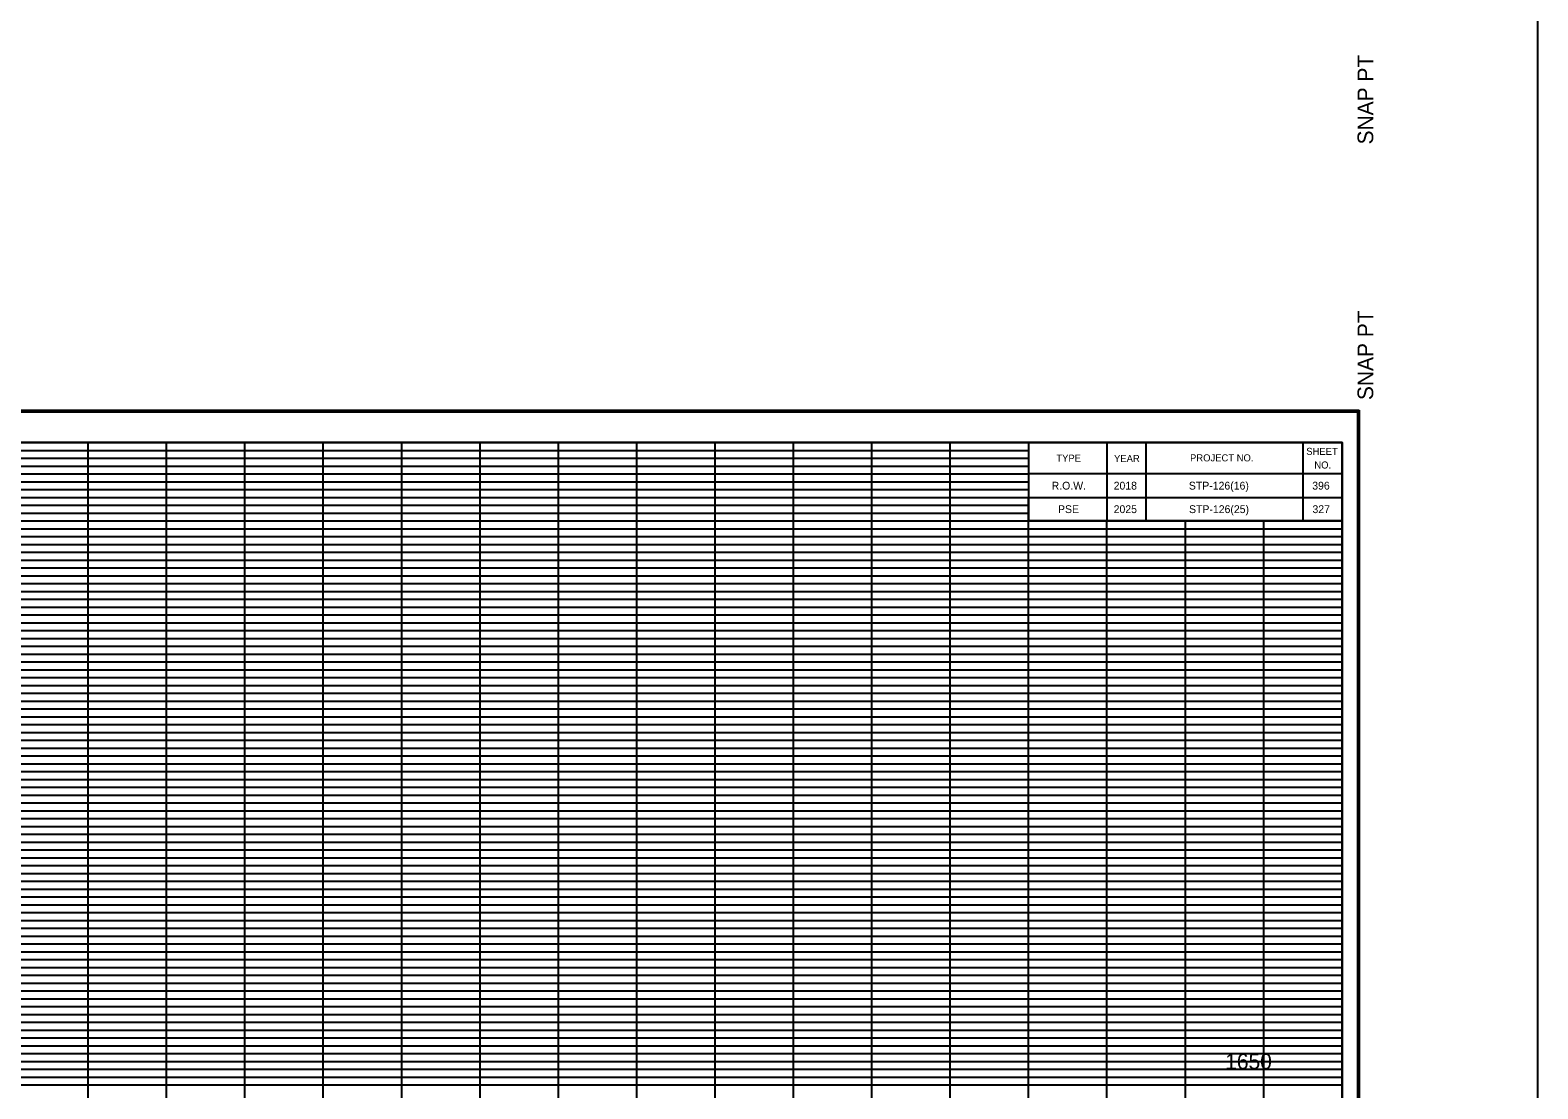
# Model space of a CAD drawing. Extents: x 955 to 1375, y 1248 to 3657.
# Drawn here: x 1152.6 to 1345, y 2477.5 to 2612.7 of the extents above; entities that cross this region are included whole.
import ezdxf

# ---------------------------------------------------------------- set-up
doc = ezdxf.new("R2010")
doc.units = 0
for name, color, linetype in [('DESIGN - SCRATCH - User 1', 7, 'Continuous'), ('DESIGN - SHEET - Corner Text', 7, 'Continuous'), ('DESIGN - SHEET - Light Grid', 7, 'Continuous'), ('DESIGN - SHEET - Linework', 7, 'Continuous'), ('DESIGN - SHEET - Plot Shape', 7, 'Continuous'), ('DESIGN - TYPICAL - Text', 7, 'Continuous'), ('DESIGN - UTILITIES - Cable (Overhead) with Text', 7, 'Continuous'), ('SURVEY - NON-TRANSPORTATION - Features Text', 7, 'Continuous')]:
    doc.layers.add(name, color=color, linetype=linetype)

# ---------------------------------------------------------------- blocks, each defined once
blk = doc.blocks.new('XSTSHT')
at = {"layer": 'DESIGN - SCRATCH - User 1'}
for p, q in [((28.5, 20.45), (28.5, 20.45)), ((29.24, 20.45), (29.24, 20.45)), ((30.49, 20.45), (30.49, 20.45)), ((31.74, 20.45), (31.74, 20.45)), ((28.5, 20.15), (28.5, 20.15)), ((29.24, 20.15), (29.24, 20.15)), ((30.49, 20.15), (30.49, 20.15)), ((31.74, 20.15), (31.74, 20.15))]:
    blk.add_line(p, q, dxfattribs=at)
at = {"layer": 'DESIGN - SHEET - Light Grid'}
for p, q in [((8, 20.9), (16, 20.9)), ((8, 20.8), (16, 20.8)), ((16, 20.9), (24, 20.9)), ((16, 20.8), (24, 20.8)), ((24, 20.9), (28, 20.9)), ((24, 20.8), (28, 20.8)), ((8, 20.7), (16, 20.7)), ((8, 20.6), (16, 20.6)), ((16, 20.7), (24, 20.7)), ((16, 20.6), (24, 20.6)), ((24, 20.7), (28, 20.7)), ((24, 20.6), (28, 20.6)), ((8, 20.5), (16, 20.5)), ((8, 20.4), (16, 20.4)), ((16, 20.5), (24, 20.5)), ((16, 20.4), (24, 20.4)), ((24, 20.5), (28, 20.5)), ((24, 20.4), (28, 20.4)), ((8, 20.3), (16, 20.3)), ((16, 20.3), (24, 20.3)), ((24, 20.3), (28, 20.3)), ((8, 20.2), (16, 20.2)), ((8, 20.1), (16, 20.1)), ((16, 20.2), (24, 20.2)), ((16, 20.1), (24, 20.1)), ((24, 20.2), (28, 20.2)), ((24, 20.1), (28, 20.1)), ((8, 19.9), (16, 19.9)), ((16, 19.9), (24, 19.9)), ((24, 19.9), (32, 19.9)), ((8, 19.8), (16, 19.8)), ((8, 19.7), (16, 19.7)), ((16, 19.8), (24, 19.8)), ((16, 19.7), (24, 19.7)), ((24, 19.8), (32, 19.8)), ((24, 19.7), (32, 19.7)), ((8, 19.6), (16, 19.6)), ((8, 19.5), (16, 19.5)), ((16, 19.6), (24, 19.6)), ((16, 19.5), (24, 19.5)), ((24, 19.6), (32, 19.6)), ((24, 19.5), (32, 19.5)), ((8, 19.4), (16, 19.4)), ((8, 19.3), (16, 19.3)), ((16, 19.4), (24, 19.4)), ((16, 19.3), (24, 19.3)), ((24, 19.4), (32, 19.4)), ((24, 19.3), (32, 19.3)), ((8, 19.2), (16, 19.2)), ((8, 19.1), (16, 19.1)), ((16, 19.2), (24, 19.2)), ((16, 19.1), (24, 19.1)), ((24, 19.2), (32, 19.2)), ((24, 19.1), (32, 19.1)), ((8, 18.9), (16, 18.9)), ((16, 18.9), (24, 18.9)), ((24, 18.9), (32, 18.9)), ((8, 18.8), (16, 18.8)), ((8, 18.7), (16, 18.7)), ((16, 18.8), (24, 18.8)), ((16, 18.7), (24, 18.7)), ((24, 18.8), (32, 18.8)), ((24, 18.7), (32, 18.7)), ((8, 18.6), (16, 18.6)), ((8, 18.5), (16, 18.5)), ((16, 18.6), (24, 18.6)), ((16, 18.5), (24, 18.5)), ((24, 18.6), (32, 18.6)), ((24, 18.5), (32, 18.5)), ((8, 18.4), (16, 18.4)), ((8, 18.3), (16, 18.3)), ((16, 18.4), (24, 18.4)), ((16, 18.3), (24, 18.3)), ((24, 18.4), (32, 18.4)), ((24, 18.3), (32, 18.3)), ((8, 18.2), (16, 18.2)), ((8, 18.1), (16, 18.1)), ((16, 18.2), (24, 18.2)), ((16, 18.1), (24, 18.1)), ((24, 18.2), (32, 18.2)), ((24, 18.1), (32, 18.1)), ((8, 17.9), (16, 17.9)), ((16, 17.9), (24, 17.9)), ((24, 17.9), (32, 17.9)), ((8, 17.8), (16, 17.8)), ((8, 17.7), (16, 17.7)), ((16, 17.8), (24, 17.8)), ((16, 17.7), (24, 17.7)), ((24, 17.8), (32, 17.8)), ((24, 17.7), (32, 17.7)), ((8, 17.6), (16, 17.6)), ((16, 17.6), (24, 17.6)), ((24, 17.6), (32, 17.6)), ((8, 17.5), (16, 17.5)), ((8, 17.4), (16, 17.4)), ((16, 17.5), (24, 17.5)), ((16, 17.4), (24, 17.4)), ((24, 17.5), (32, 17.5)), ((24, 17.4), (32, 17.4)), ((8, 17.3), (16, 17.3)), ((8, 17.2), (16, 17.2)), ((16, 17.3), (24, 17.3)), ((16, 17.2), (24, 17.2)), ((24, 17.3), (32, 17.3)), ((24, 17.2), (32, 17.2)), ((8, 17.1), (16, 17.1)), ((16, 17.1), (24, 17.1)), ((24, 17.1), (32, 17.1)), ((8, 16.9), (16, 16.9)), ((8, 16.8), (16, 16.8)), ((16, 16.9), (24, 16.9)), ((16, 16.8), (24, 16.8)), ((24, 16.9), (32, 16.9)), ((24, 16.8), (32, 16.8)), ((8, 16.7), (16, 16.7)), ((8, 16.6), (16, 16.6)), ((16, 16.7), (24, 16.7)), ((16, 16.6), (24, 16.6)), ((24, 16.7), (32, 16.7)), ((24, 16.6), (32, 16.6)), ((8, 16.5), (16, 16.5)), ((8, 16.4), (16, 16.4)), ((16, 16.5), (24, 16.5)), ((16, 16.4), (24, 16.4)), ((24, 16.5), (32, 16.5)), ((24, 16.4), (32, 16.4)), ((8, 16.3), (16, 16.3)), ((8, 16.2), (16, 16.2)), ((16, 16.3), (24, 16.3)), ((16, 16.2), (24, 16.2)), ((24, 16.3), (32, 16.3)), ((24, 16.2), (32, 16.2)), ((8, 16.1), (16, 16.1)), ((16, 16.1), (24, 16.1)), ((24, 16.1), (32, 16.1)), ((8, 15.9), (16, 15.9)), ((8, 15.8), (16, 15.8)), ((16, 15.9), (24, 15.9)), ((16, 15.8), (24, 15.8)), ((24, 15.9), (32, 15.9)), ((24, 15.8), (32, 15.8)), ((8, 15.7), (16, 15.7)), ((8, 15.6), (16, 15.6)), ((16, 15.7), (24, 15.7)), ((16, 15.6), (24, 15.6)), ((24, 15.7), (32, 15.7)), ((24, 15.6), (32, 15.6)), ((8, 15.5), (16, 15.5)), ((8, 15.4), (16, 15.4)), ((16, 15.5), (24, 15.5)), ((16, 15.4), (24, 15.4)), ((24, 15.5), (32, 15.5)), ((24, 15.4), (32, 15.4)), ((8, 15.3), (16, 15.3)), ((8, 15.2), (16, 15.2)), ((16, 15.3), (24, 15.3)), ((16, 15.2), (24, 15.2)), ((24, 15.3), (32, 15.3)), ((24, 15.2), (32, 15.2)), ((8, 15.1), (16, 15.1)), ((16, 15.1), (24, 15.1)), ((24, 15.1), (32, 15.1)), ((8, 14.9), (16, 14.9)), ((16, 14.9), (24, 14.9)), ((24, 14.9), (32, 14.9)), ((8, 14.8), (16, 14.8)), ((8, 14.7), (16, 14.7)), ((16, 14.8), (24, 14.8)), ((16, 14.7), (24, 14.7)), ((24, 14.8), (32, 14.8)), ((24, 14.7), (32, 14.7)), ((8, 14.6), (16, 14.6)), ((8, 14.5), (16, 14.5)), ((16, 14.6), (24, 14.6)), ((16, 14.5), (24, 14.5)), ((24, 14.6), (32, 14.6)), ((24, 14.5), (32, 14.5)), ((8, 14.4), (16, 14.4)), ((8, 14.3), (16, 14.3)), ((16, 14.4), (24, 14.4)), ((16, 14.3), (24, 14.3)), ((24, 14.4), (32, 14.4)), ((24, 14.3), (32, 14.3)), ((8, 14.2), (16, 14.2)), ((8, 14.1), (16, 14.1)), ((16, 14.2), (24, 14.2)), ((16, 14.1), (24, 14.1)), ((24, 14.2), (32, 14.2)), ((24, 14.1), (32, 14.1)), ((8, 13.9), (16, 13.9)), ((16, 13.9), (24, 13.9)), ((24, 13.9), (32, 13.9)), ((8, 13.8), (16, 13.8)), ((8, 13.7), (16, 13.7)), ((16, 13.8), (24, 13.8)), ((16, 13.7), (24, 13.7)), ((24, 13.8), (32, 13.8)), ((24, 13.7), (32, 13.7)), ((8, 13.6), (16, 13.6)), ((8, 13.5), (16, 13.5)), ((16, 13.6), (24, 13.6)), ((16, 13.5), (24, 13.5)), ((24, 13.6), (32, 13.6)), ((24, 13.5), (32, 13.5)), ((8, 13.4), (16, 13.4)), ((8, 13.3), (16, 13.3)), ((16, 13.4), (24, 13.4)), ((16, 13.3), (24, 13.3)), ((24, 13.4), (32, 13.4)), ((24, 13.3), (32, 13.3)), ((8, 13.2), (16, 13.2)), ((8, 13.1), (16, 13.1)), ((16, 13.2), (24, 13.2)), ((16, 13.1), (24, 13.1)), ((24, 13.2), (32, 13.2)), ((24, 13.1), (32, 13.1)), ((8, 12.9), (16, 12.9)), ((16, 12.9), (24, 12.9)), ((24, 12.9), (32, 12.9)), ((8, 12.8), (16, 12.8)), ((16, 12.8), (24, 12.8)), ((24, 12.8), (32, 12.8))]:
    blk.add_line(p, q, dxfattribs=at)
at = {"layer": 'DESIGN - SHEET - Linework'}
for p, q in [((-1.823, 21.414), (32.217, 21.414)), ((32.217, 21.414), (32.217, -0.414)), ((16, 0), (16, 21)), ((17, 0), (17, 21)), ((18, 0), (18, 21)), ((19, 0), (19, 21)), ((20, 0), (20, 21)), ((21, 0), (21, 21)), ((22, 0), (22, 21)), ((23, 0), (23, 21)), ((24, 0), (24, 21)), ((25, 0), (25, 21)), ((26, 0), (26, 21)), ((27, 0), (27, 21)), ((0, 20), (28, 20)), ((28, 0), (28, 20)), ((29, 0), (29, 20)), ((30, 0), (30, 20)), ((31, 0), (31, 20)), ((0, 19), (32, 19)), ((0, 18), (32, 18)), ((0, 17), (32, 17)), ((0, 16), (32, 16)), ((0, 15), (32, 15)), ((0, 14), (32, 14)), ((0, 13), (32, 13))]:
    blk.add_line(p, q, dxfattribs=at)
for points in [[(0, 21), (0, 0), (32, 0), (32, 21), (0, 21)], [(28, 21), (28, 20), (32, 20), (32, 21), (31.5, 21), (31.5, 20), (29.5, 20), (29.5, 21), (29, 21), (29, 20), (32, 20), (28, 20), (28, 20.3), (32, 20.3), (32, 20.6), (28, 20.6)]]:
    blk.add_lwpolyline(points, dxfattribs=at)
at = {"layer": 'DESIGN - SHEET - Plot Shape'}
for points in [[(-1.803, 21.394), (32.197, 21.394), (32.197, -0.394), (-1.803, -0.394)], [(-0.85, 21), (32, 21), (32, -0.25), (-0.85, -0.25)]]:
    blk.add_lwpolyline(points, close=True, dxfattribs=at)
at = {"layer": 'DESIGN - SHEET - Corner Text'}
for s, p in [('  SNAP PT', (32.397, 21.394)), ('SNAP PT  ', (32.397, -2.194))]:
    blk.add_text(s, height=0.2, rotation=90, dxfattribs=at).set_placement(p)
for s, p in [('TYPE', (28.354, 20.756)), ('YEAR', (29.09, 20.752)), ('PROJECT NO.', (30.06, 20.76)), ('SHEET', (31.543, 20.843)), ('NO.', (31.646, 20.669))]:
    blk.add_text(s, height=0.09, dxfattribs=at).set_placement(p)

msp = doc.modelspace()

# ---------------------------------------------------------------- linework, layer by layer
at = {"layer": 'DESIGN - SHEET - Plot Shape'}
msp.add_lwpolyline([(991.5, 2347.5), (1320, 2347.5), (1320, 2560), (991.5, 2560)], close=True, dxfattribs=at)
at = {"layer": 'SURVEY - NON-TRANSPORTATION - Features Text'}
msp.add_lwpolyline([(955.41, 1505.76), (1344.98, 1505.76), (1344.98, 3398.01), (955.41, 3398.01)], close=True, dxfattribs=at)

# ---------------------------------------------------------------- block references
at = {"layer": 'DESIGN - UTILITIES - Cable (Overhead) with Text', "xscale": 10, "yscale": 10}
for p in [(1000, 2620), (1000, 2350)]:
    msp.add_blockref('XSTSHT', p, dxfattribs=at)

# ---------------------------------------------------------------- texts
at = {"layer": 'DESIGN - SHEET - Corner Text'}
for s, p in [('R.O.W.', (1282.94, 2554)), ('2018', (1290.85, 2554)), ('STP-126(16)', (1300.45, 2554)), ('396', (1316.19, 2554)), ('PSE', (1283.75, 2551)), ('2025', (1290.85, 2551)), ('STP-126(25)', (1300.47, 2551)), ('327', (1316.22, 2551))]:
    msp.add_text(s, height=1, dxfattribs=at).set_placement(p)
at = {"layer": 'DESIGN - TYPICAL - Text'}
msp.add_text('     1650     ', height=2, dxfattribs=at).set_placement((1301.37, 2480))

doc.saveas('drawing.dxf')
